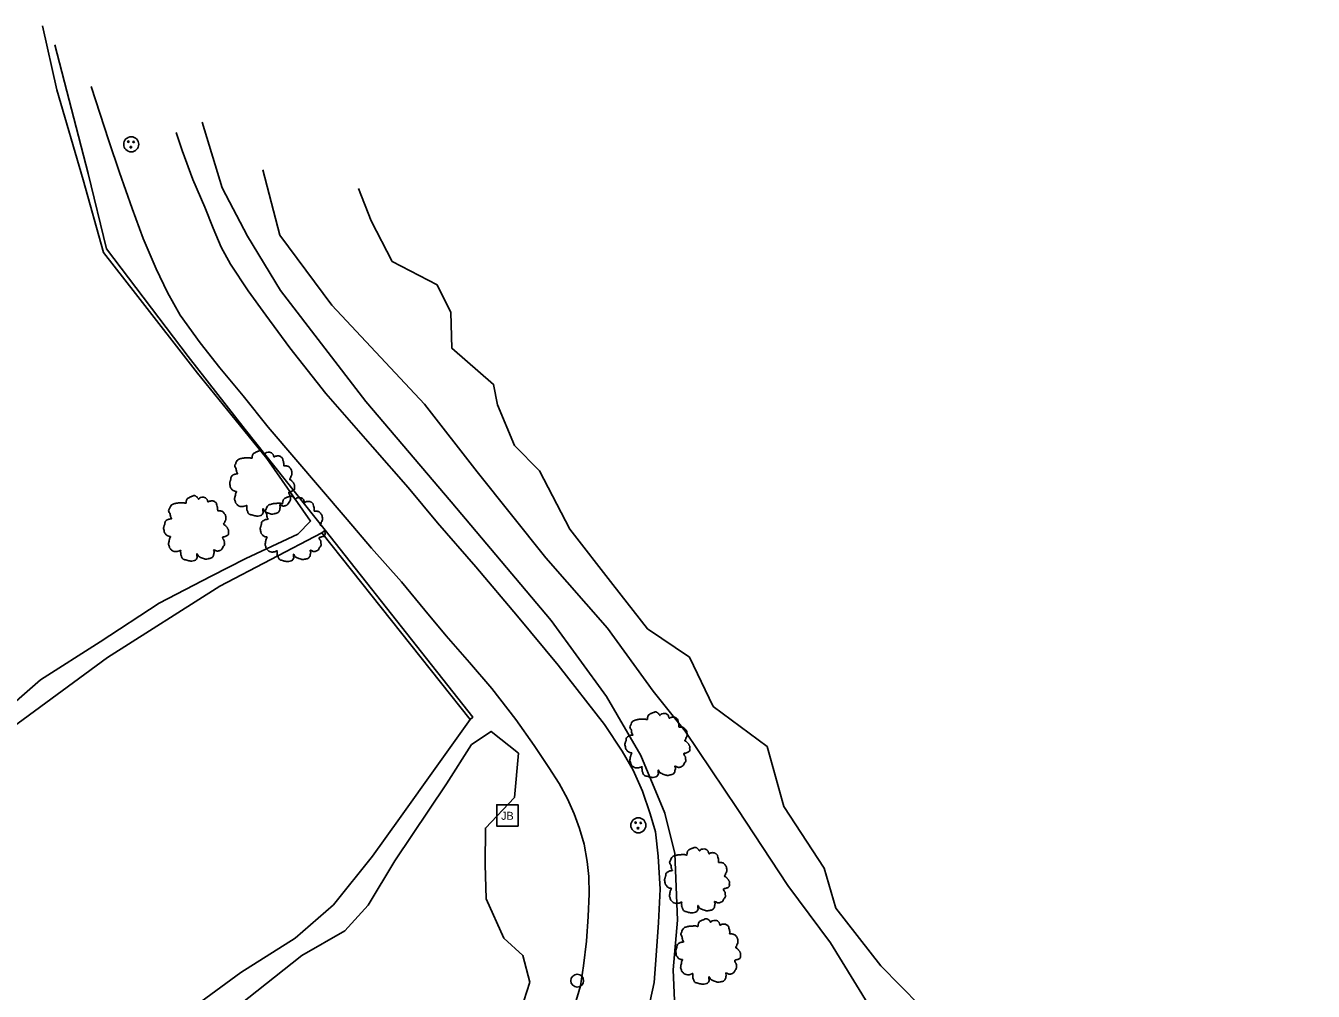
# Model space of a CAD drawing. Extents: x 2160437 to 2172832, y 205694 to 212444.
# Drawn here: x 2171419 to 2171720.6, y 208038.8 to 208265 of the extents above; entities that cross this region are included whole.
import ezdxf

# ---------------------------------------------------------------- set-up
doc = ezdxf.new("R2010")
doc.units = 0
for name, color, linetype in [('Default', 7, 'Continuous'), ('RD_EX_Bldg_Walls', 7, 'Continuous'), ('RD_EX_DR_Inlet', 7, 'Continuous'), ('RD_EX_GuardRail', 7, 'Continuous'), ('RD_EX_H2O', 7, 'Continuous'), ('RD_EX_Road', 7, 'Continuous'), ('RD_EX_Road_Post', 7, 'Continuous'), ('RD_EX_VEG', 7, 'Continuous'), ('RD_EX_VEG_ShrubLine', 7, 'Continuous'), ('RD_EX_VEG_TreeLine', 7, 'Continuous')]:
    doc.layers.add(name, color=color, linetype=linetype)

# ---------------------------------------------------------------- blocks, each defined once
blk = doc.blocks.new('MH')
at = {"layer": 'RD_EX_DR_Inlet'}
for centre, radius in [((0, 0), 1.75), ((-0.66, 0.63), 0.175), ((0.56, 0.56), 0.175), ((-0.09, -0.66), 0.175)]:
    blk.add_circle(centre, radius, dxfattribs=at)
blk = doc.blocks.new('POST')
at = {"layer": 'Default'}
for start, end in [(90, 270), (270, 90)]:
    blk.add_arc((0, 0), 0.0417, start, end, dxfattribs=at)
blk = doc.blocks.new('T2')
at = {"layer": 'RD_EX_VEG'}
for points in [[(0.05, 7.21), (-0.25, 7.24), (-0.57, 7.14), (-0.82, 7.04), (-1.05, 6.96), (-1.27, 6.86), (-1.57, 6.69), (-1.8, 6.49), (-1.92, 6.24), (-1.97, 6.01), (-2.02, 5.74), (-2.02, 5.56), (-2.15, 5.54), (-2.3, 5.56), (-2.55, 5.64), (-2.8, 5.64), (-3.05, 5.64), (-3.4, 5.61), (-3.75, 5.61), (-4.02, 5.56), (-4.35, 5.51), (-4.72, 5.39), (-5.07, 5.26), (-5.37, 5.01), (-5.62, 4.54), (-5.75, 4.19), (-5.9, 3.94), (-5.75, 3.49), (-5.57, 3.14), (-5.55, 2.94), (-5.47, 2.52), (-5.37, 2.29), (-5.25, 2.09), (-5.32, 2.07), (-5.7, 2.02), (-6, 1.92), (-6.42, 1.69), (-6.64, 1.47), (-6.74, 1.14), (-6.77, 0.79), (-6.87, 0.59), (-6.94, 0.32), (-6.97, 0.24), (-7.02, -0.08), (-6.92, -0.53), (-6.89, -0.88), (-6.77, -1.11), (-6.62, -1.28), (-6.44, -1.53), (-6.05, -1.76), (-5.72, -1.86), (-5.52, -1.88), (-5.7, -2.38), (-5.75, -2.73), (-5.87, -3.13), (-5.87, -3.21), (-5.92, -3.68), (-5.77, -4.01), (-5.7, -4.38), (-5.52, -4.61), (-5.25, -4.91), (-4.92, -5.13), (-4.42, -5.26), (-4.02, -5.23), (-3.45, -5.06), (-3.2, -4.98), (-3.22, -5.16), (-3.2, -5.53), (-3.2, -5.96), (-3.05, -6.28), (-2.95, -6.56), (-2.8, -6.81), (-2.47, -7.03), (-2.07, -7.11), (-1.65, -7.26), (-1.2, -7.33), (-0.7, -7.36), (-0.1, -7.21), (0.18, -7.08), (0.28, -6.91), (0.48, -6.53), (0.43, -6.31), (0.45, -5.71), (0.55, -5.88), (0.73, -6.23), (1.23, -6.53), (1.63, -6.71), (2.1, -6.86), (2.4, -6.93), (2.88, -6.86), (3.25, -6.78), (3.63, -6.66), (3.93, -6.38), (4.1, -6.11), (4.15, -5.83), (4.23, -5.46), (4.28, -5.28)], [(4.28, -5.28), (4.2, -5.11), (4.15, -4.86), (4.23, -4.88), (4.4, -4.93), (4.68, -5.06), (4.9, -5.13), (5.23, -5.11), (5.5, -5.01), (5.95, -4.73), (6.22, -4.26), (6.5, -3.86), (6.57, -3.53), (6.52, -3.31), (6.5, -2.81), (6.3, -2.56), (6.25, -2.43), (6.15, -2.03), (6.22, -1.98), (6.5, -1.93), (6.87, -1.81), (7.15, -1.68), (7.37, -1.51), (7.45, -1.28), (7.42, -0.88), (7.47, -0.48), (7.4, -0.33), (7.3, -0.18), (7.22, 0.02), (7.07, 0.17), (6.97, 0.32), (6.87, 0.42), (6.75, 0.57), (6.57, 0.69), (6.42, 0.74), (6.37, 0.89), (6.52, 1.09), (6.57, 1.19), (6.6, 1.42), (6.82, 1.77), (6.87, 2.17), (6.82, 2.59), (6.77, 2.87), (6.62, 3.14), (6.42, 3.39), (6.3, 3.56), (6.12, 3.69), (5.8, 3.81), (5.55, 3.86), (5.2, 3.86), (5, 3.91), (5.03, 3.96), (5.03, 4.11), (5.03, 4.39), (4.95, 4.84), (4.8, 5.34), (4.8, 5.36), (4.7, 5.61), (4.48, 5.81), (4.3, 5.91), (4.1, 6.04), (3.85, 6.06), (3.55, 6.06), (3.28, 6.01), (3.08, 5.91), (2.9, 5.79), (2.83, 5.94), (2.73, 6.24), (2.68, 6.39), (2.53, 6.56), (2.3, 6.76), (1.85, 6.89), (1.23, 6.81), (0.93, 6.61), (0.78, 6.44), (0.73, 6.56), (0.53, 6.76), (0.43, 6.94), (0.25, 7.06), (0.1, 7.16), (0, 7.21)]]:
    blk.add_spline(points, degree=3, dxfattribs=at)

msp = doc.modelspace()

# ---------------------------------------------------------------- linework, layer by layer
at = {"layer": 'RD_EX_Bldg_Walls'}
msp.add_lwpolyline([(2171523.08, 208102.45), (2171488.4, 208146.22), (2171489.19, 208146.83), (2171523.77, 208103.06)], close=True, dxfattribs=at)
at = {"layer": 'RD_EX_DR_Inlet'}
msp.add_line((2171534.34, 208077.51), (2171534.34, 208082.51), dxfattribs=at)
msp.add_lwpolyline([(2171534.34, 208077.51), (2171534.34, 208082.51), (2171529.34, 208082.51), (2171529.34, 208077.51)], close=True, dxfattribs=at)
at = {"layer": 'RD_EX_GuardRail'}
msp.add_lwpolyline([(2171425.85, 208260.51), (2171433.67, 208230.38), (2171437.93, 208212.7), (2171457.05, 208187.51), (2171470.38, 208170.45), (2171489.19, 208146.83), (2171523.77, 208103.06)], dxfattribs=at)
at = {"layer": 'RD_EX_H2O'}
for points in [[(2171488.4, 208146.22), (2171464.49, 208133.75), (2171438.19, 208116.98), (2171415.73, 208100.57)], [(2171410.68, 207993.47), (2171428.5, 208008.24), (2171439.53, 208020), (2171451.85, 208030.35), (2171469.4, 208043.2), (2171482.14, 208051.23), (2171491.07, 208059.1), (2171500.21, 208070.51), (2171506.6, 208079.31), (2171515.3, 208091.53), (2171523.08, 208102.45)]]:
    msp.add_lwpolyline(points, dxfattribs=at)
at = {"layer": 'RD_EX_Road'}
for points in [[(2171434.38, 208250.76), (2171438.46, 208238.01), (2171441.01, 208230.64), (2171443.95, 208222.17), (2171446.55, 208215.12), (2171449.56, 208208.02), (2171452.19, 208202.48), (2171455.2, 208197.21), (2171459.9, 208190.73), (2171464.45, 208184.89), (2171469.92, 208178.26), (2171475.79, 208170.99), (2171494.28, 208149.31), (2171499.99, 208142.59), (2171507, 208134.75), (2171512.49, 208128.11), (2171517.46, 208122.05), (2171522.92, 208115.86), (2171528.18, 208109.71), (2171533.8, 208102.5), (2171538.07, 208096.38), (2171541.53, 208091.26), (2171543.93, 208087.48), (2171545.92, 208083.93), (2171547.44, 208080.37), (2171548.74, 208076.92), (2171549.83, 208073.25), (2171550.52, 208069.26), (2171550.87, 208065.71), (2171550.95, 208061.66), (2171550.75, 208056.37), (2171550.37, 208050.6), (2171549.68, 208044.77), (2171548.93, 208040.11), (2171547.52, 208035.32)], [(2171565.26, 208036.61), (2171566.18, 208040.88), (2171566.71, 208047.18), (2171567.26, 208054.96), (2171567.6, 208062.74), (2171567.14, 208070.45), (2171566.54, 208076.19), (2171565.3, 208080.41), (2171563.46, 208085.73), (2171561.31, 208090.65), (2171558.72, 208095.05), (2171554.6, 208101.32), (2171543.7, 208115.22), (2171534.2, 208126.69), (2171524.41, 208138.24), (2171515.43, 208148.55), (2171508.56, 208156.79), (2171500.23, 208166.37), (2171489.33, 208178.87), (2171480.88, 208189.51), (2171475.22, 208197.23), (2171471.12, 208202.9), (2171466.98, 208209.1), (2171464.77, 208213.14), (2171462.92, 208217.59), (2171460.98, 208222.51), (2171458.15, 208228.93), (2171455.69, 208235.77), (2171454.22, 208239.99)]]:
    msp.add_lwpolyline(points, dxfattribs=at)
at = {"layer": 'RD_EX_VEG_ShrubLine'}
for points in [[(2171422.94, 208264.98), (2171426.32, 208249.94), (2171432.5, 208228.88), (2171437.26, 208211.84), (2171444.7, 208202.29), (2171459.28, 208183.63), (2171475.48, 208163.61), (2171485.72, 208148.95), (2171482.79, 208145.91), (2171470.61, 208140.18), (2171462.45, 208136.08), (2171450.27, 208129.7), (2171436.47, 208120.69), (2171422.51, 208111.76), (2171412.3, 208102.98)], [(2171571.15, 208033.09), (2171570.68, 208043.82), (2171571.68, 208055.51), (2171571.01, 208071.13), (2171568.71, 208080.55), (2171563.09, 208094.06), (2171555.06, 208107.87), (2171542.12, 208125.67), (2171518.7, 208153.5), (2171498.7, 208177), (2171478.7, 208202.95), (2171470.98, 208215.69), (2171465.06, 208226.99), (2171460.33, 208242.43)], [(2171474.59, 208231.26), (2171478.56, 208215.95), (2171490.71, 208199.54), (2171512.4, 208176.38), (2171524.78, 208160.48), (2171540.82, 208140.33), (2171555.28, 208123.87), (2171565.96, 208109.16), (2171573.48, 208099.77), (2171585.64, 208081.62), (2171597.55, 208063.58), (2171607.52, 208050.21), (2171619.04, 208031.33), (2171633.7, 208008.86), (2171640.22, 207999.53), (2171648.7, 207988.68), (2171659.25, 207978.11), (2171671.37, 207972.53), (2171682.37, 207968.48), (2171697.24, 207960.21), (2171715.83, 207949.81), (2171724.03, 207943.94)], [(2171628.49, 208035.45), (2171619.31, 208044.78), (2171608.79, 208058.3), (2171606.05, 208067.63), (2171596.58, 208082.1), (2171592.64, 208096.16), (2171580.02, 208105.54), (2171574.5, 208117.06), (2171564.62, 208123.76), (2171556.53, 208134.12), (2171546.45, 208147.03), (2171539.37, 208160.7), (2171533.46, 208166.69), (2171529.54, 208176.15), (2171528.6, 208180.97), (2171518.83, 208189.45), (2171518.6, 208197.82), (2171515.36, 208204.32), (2171504.81, 208209.79), (2171499.9, 208219.29), (2171496.96, 208226.87)]]:
    msp.add_lwpolyline(points, dxfattribs=at)
at = {"layer": 'RD_EX_VEG_TreeLine'}
msp.add_lwpolyline([(2171469.03, 208035.61), (2171483.68, 208047.24), (2171493.78, 208053), (2171499.19, 208058.98), (2171505.49, 208069.35), (2171517.6, 208087.45), (2171523.45, 208096.6), (2171528.04, 208099.69), (2171534.47, 208094.59), (2171533.47, 208084.23), (2171526.69, 208077.04), (2171526.64, 208068.49), (2171526.9, 208060.51), (2171531.01, 208051.27), (2171535.46, 208047.18), (2171537.07, 208040.93), (2171535, 208034.43)], dxfattribs=at)

# ---------------------------------------------------------------- block references
at = {"layer": 'RD_EX_DR_Inlet', "xscale": 1.0079999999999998, "yscale": 1.0079999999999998}
for p in [(2171443.73, 208237.21), (2171562.51, 208077.7)]:
    msp.add_blockref('MH', p, dxfattribs=at)
at = {"layer": 'RD_EX_Road_Post', "xscale": 36, "yscale": 36}
msp.add_blockref('POST', (2171548.19, 208041.3), dxfattribs=at)
at = {"layer": 'RD_EX_VEG', "xscale": 1.0499999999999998, "yscale": 1.0499999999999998}
for p in [(2171474.16, 208157.86), (2171458.69, 208147.32), (2171481.31, 208147.22), (2171566.73, 208096.66), (2171576.01, 208064.93), (2171578.62, 208048.21)]:
    msp.add_blockref('T2', p, dxfattribs=at)

# ---------------------------------------------------------------- texts
at = {"layer": 'RD_EX_DR_Inlet'}
msp.add_text('JB', height=1.875, dxfattribs=at).set_placement((2171530.37, 208078.99))

doc.saveas('drawing.dxf')
